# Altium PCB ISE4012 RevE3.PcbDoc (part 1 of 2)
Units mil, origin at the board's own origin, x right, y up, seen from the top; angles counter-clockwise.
Board outline 4950 x 3450 mil, 4 copper layers (Top Layer, InternalPlane1, MidLayer1, Bottom Layer), stack 59 mil thick; 143 components, 94 nets, 413 pads, 604 vias.
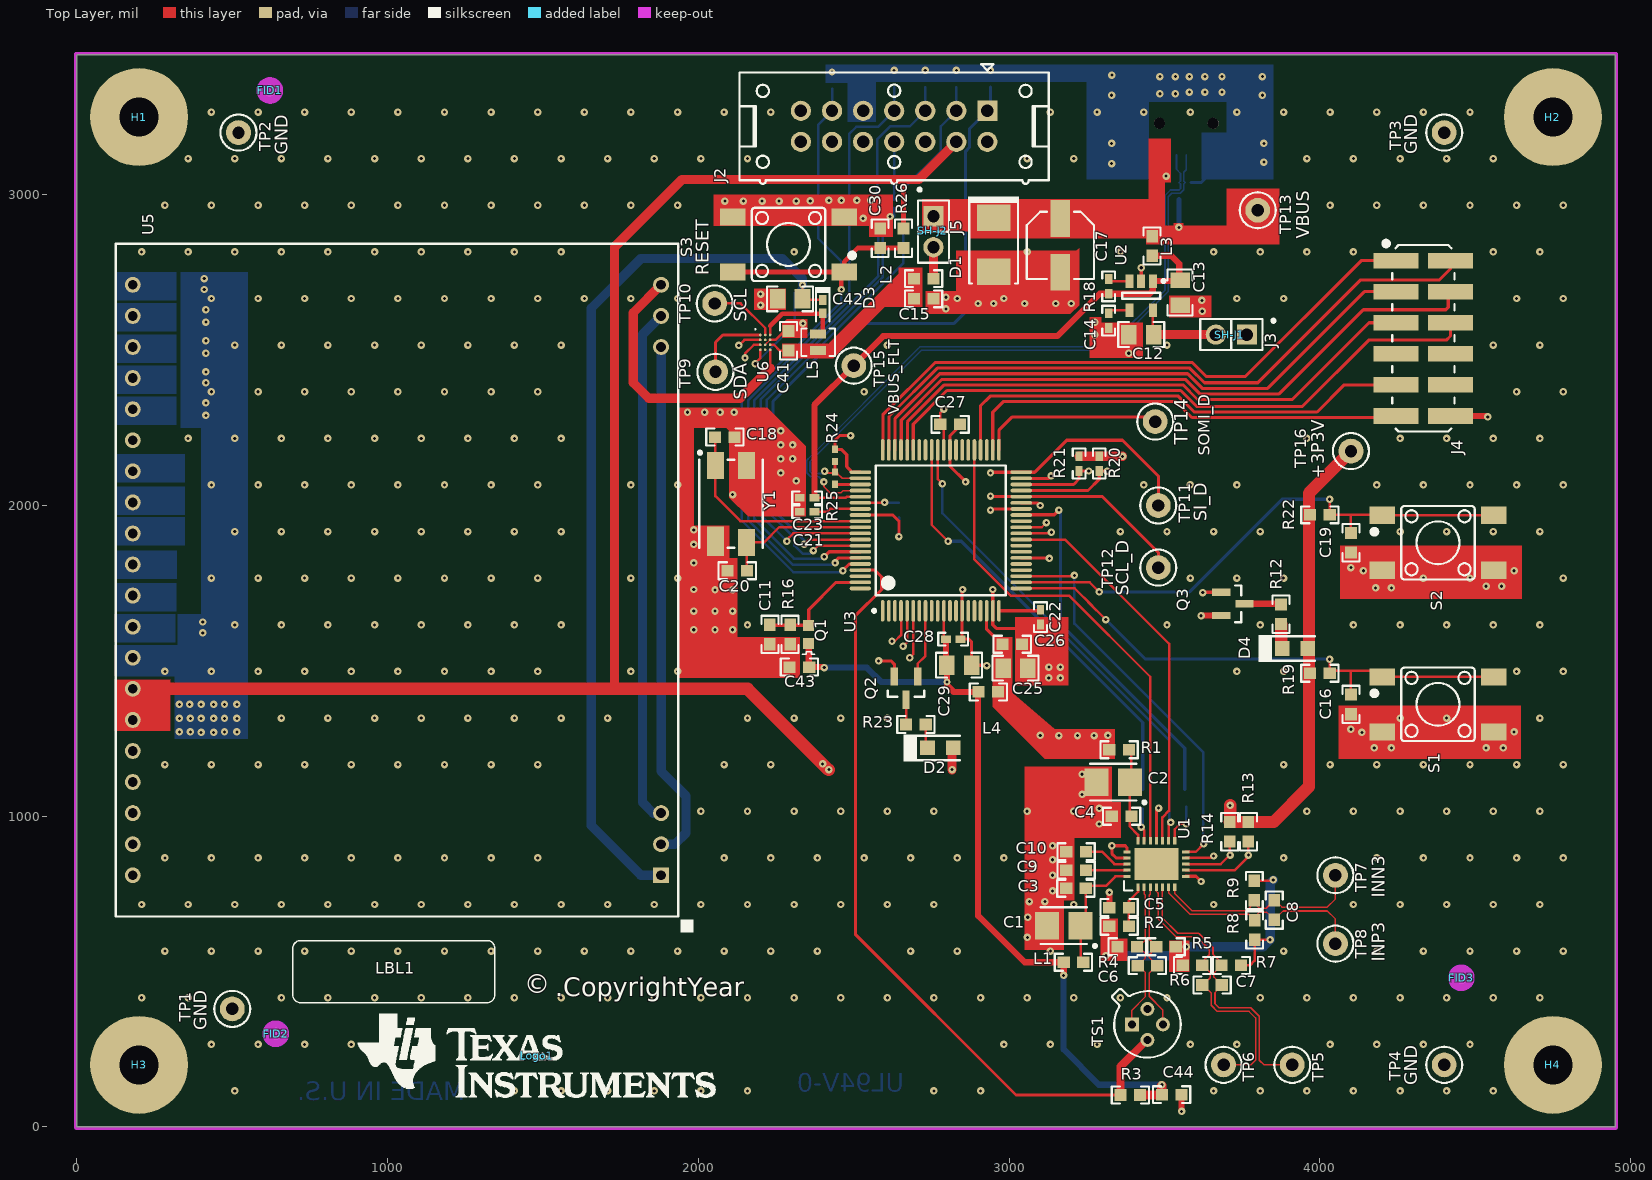
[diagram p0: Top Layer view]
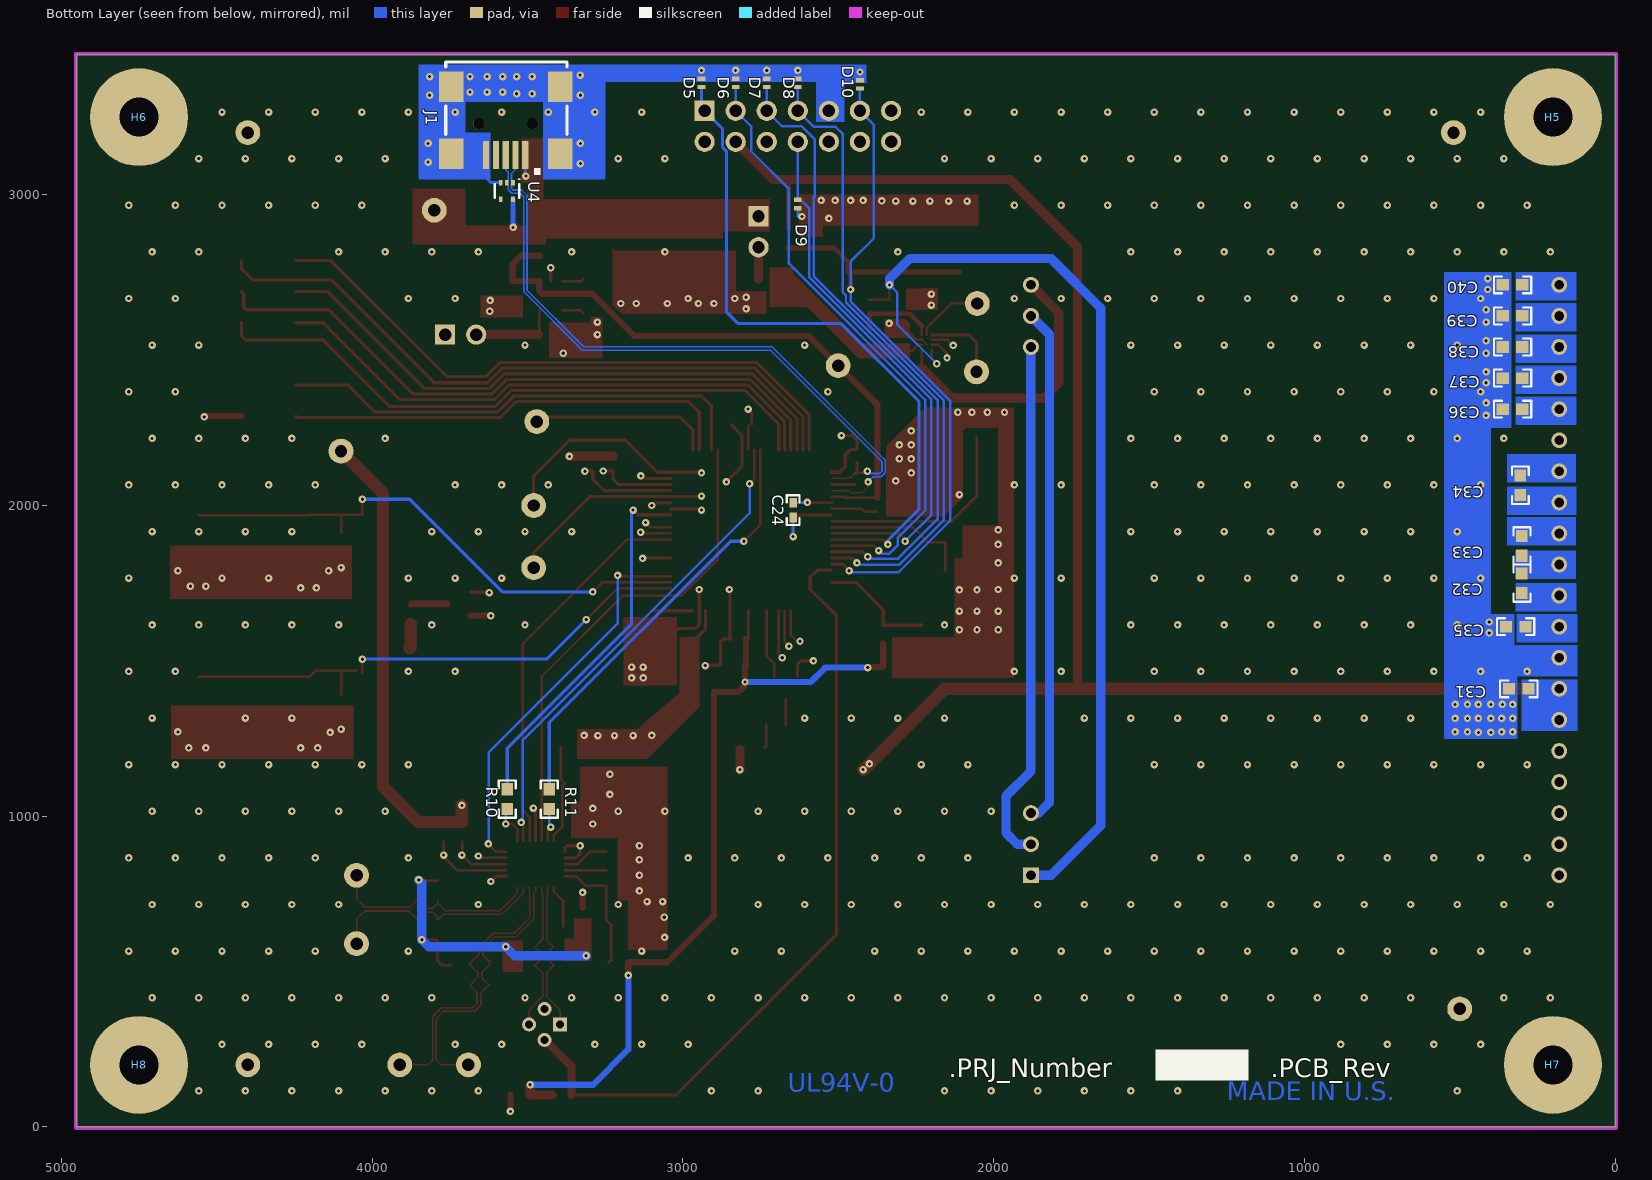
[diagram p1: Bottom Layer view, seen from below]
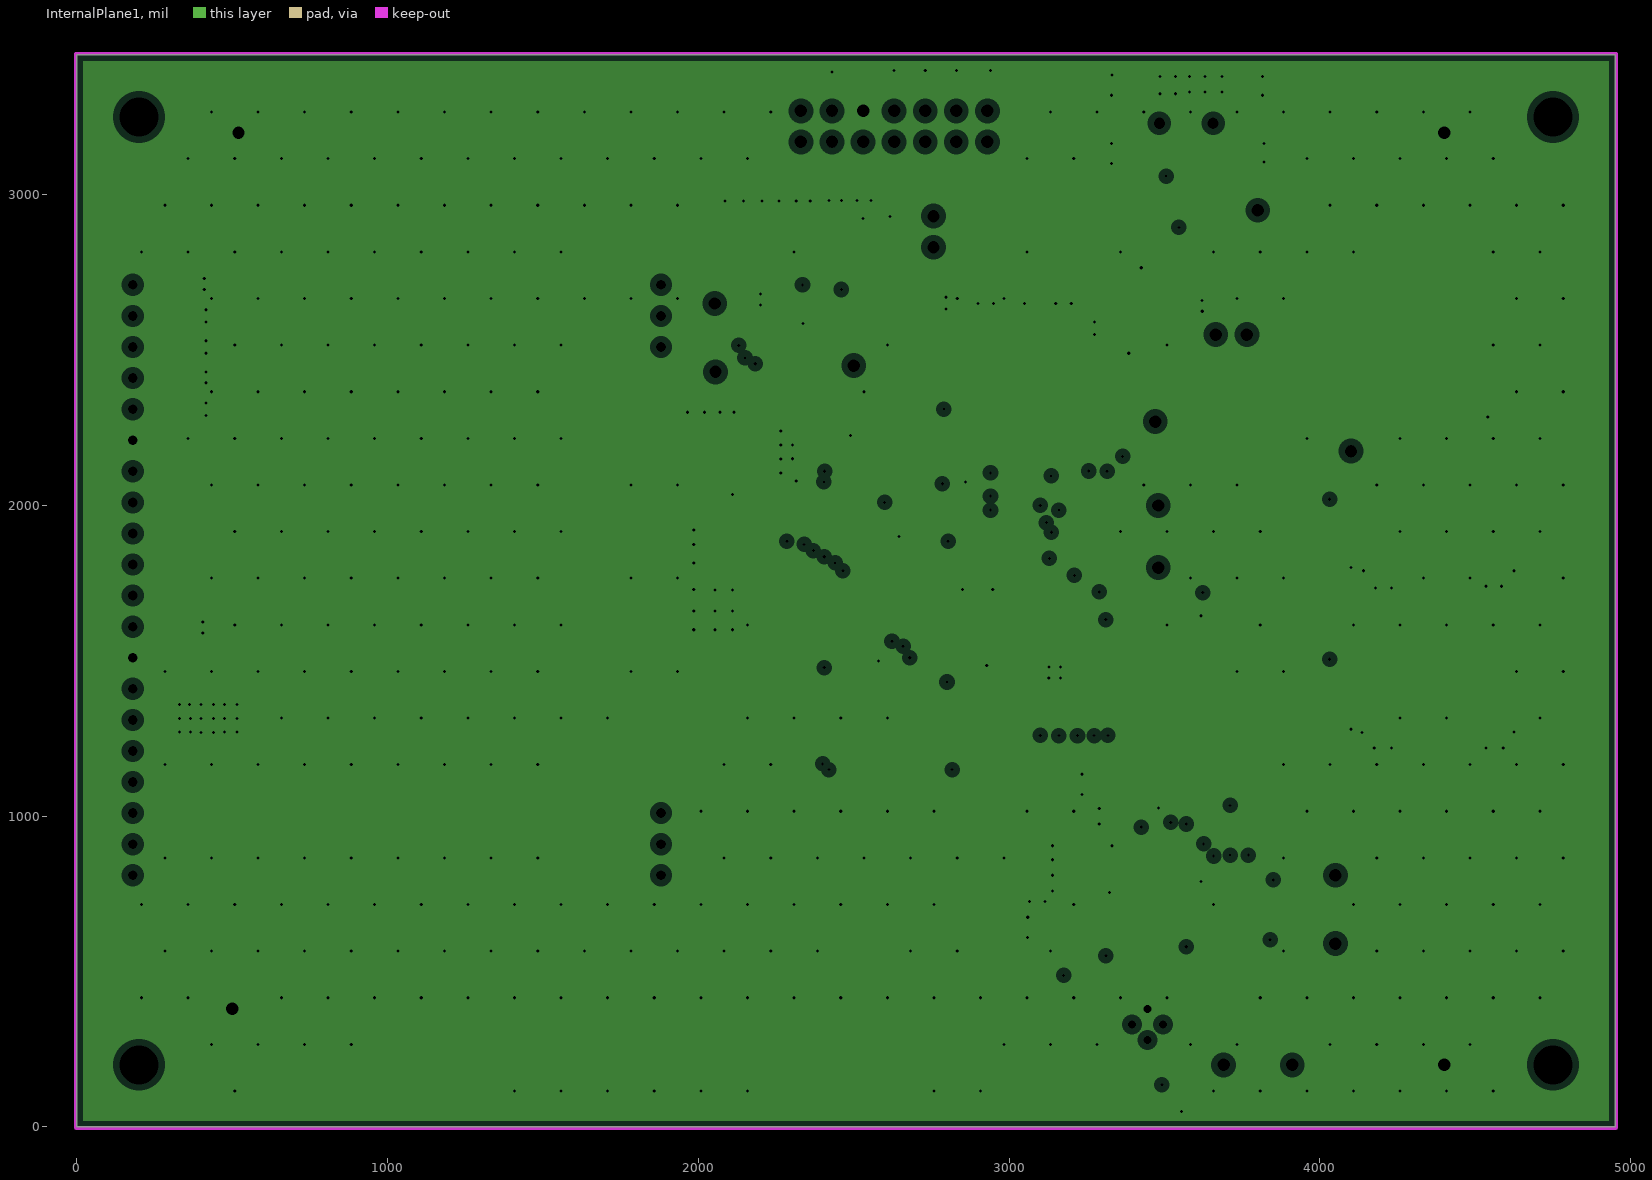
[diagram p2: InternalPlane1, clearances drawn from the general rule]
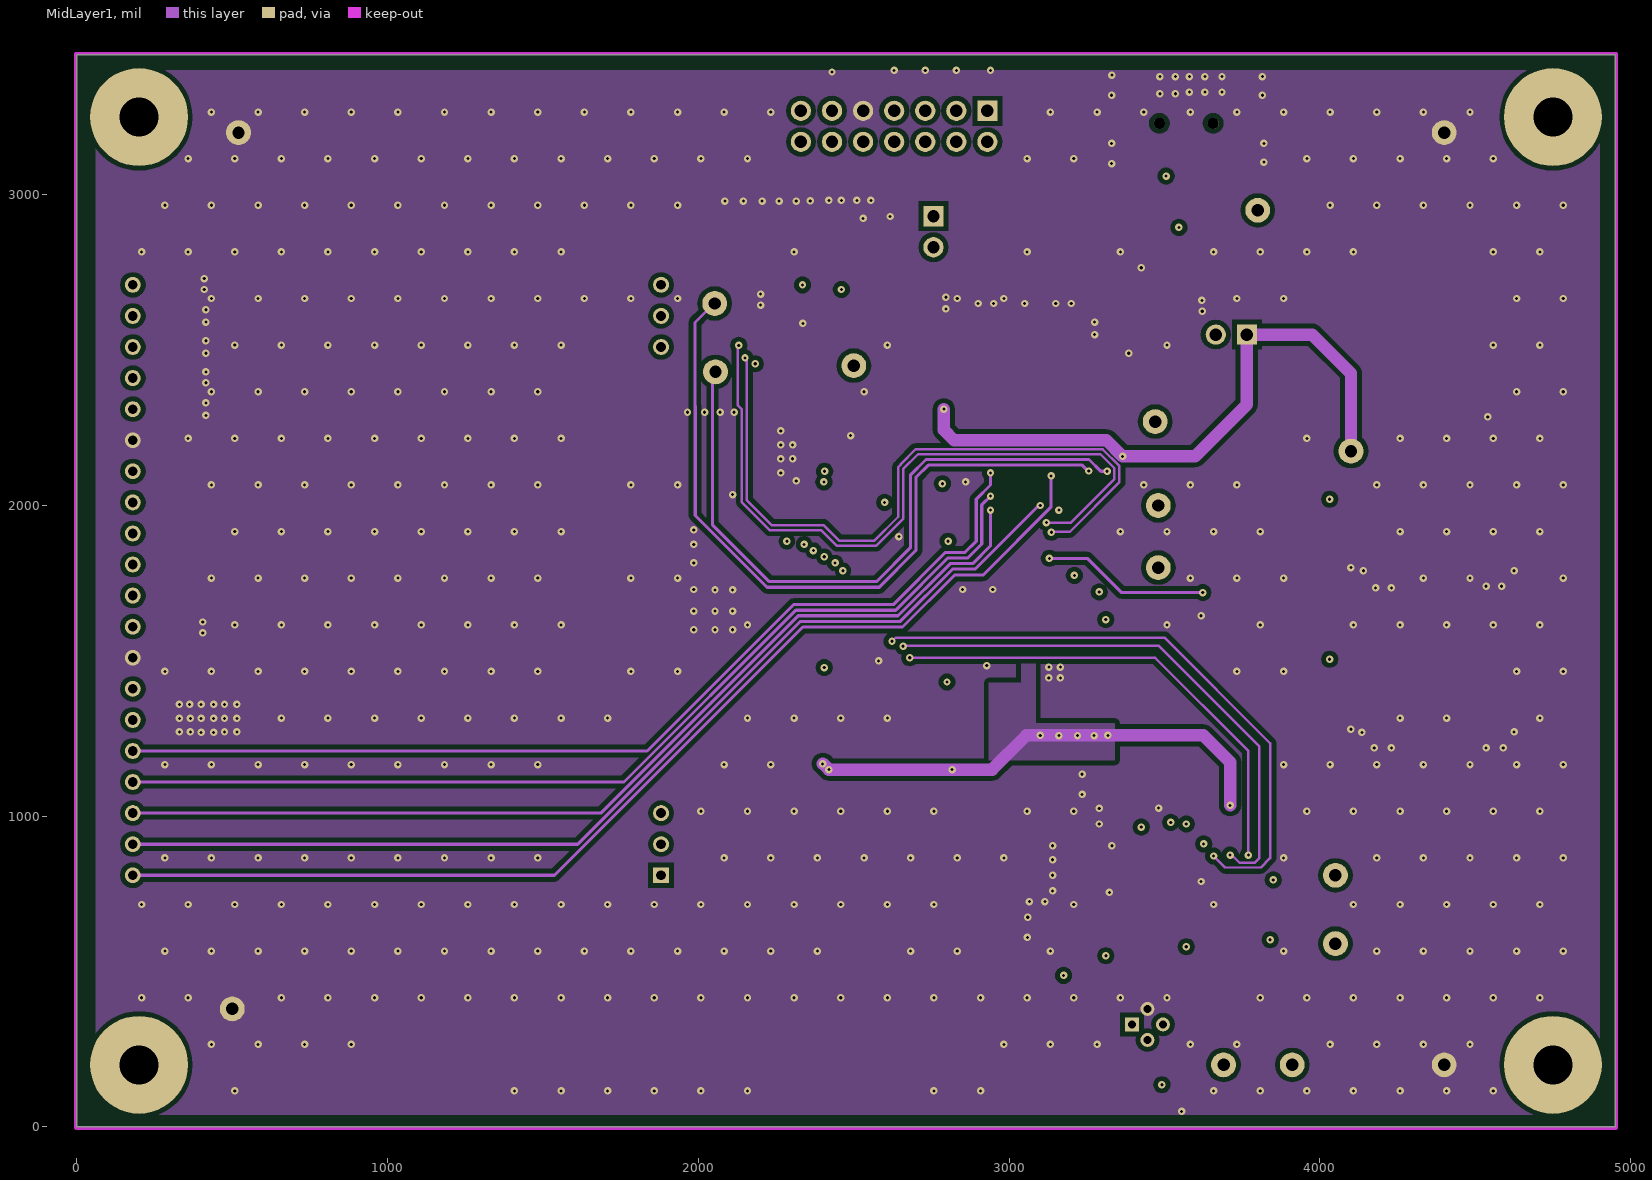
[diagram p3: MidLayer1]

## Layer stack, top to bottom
Top Layer: signal copper 1.4
Dielectric: prepreg 5.2, 370HR, Dk 4.8
InternalPlane1: plane copper 1.4, net GND
Dielectric: core 43, 370HR, Dk 4.8
MidLayer1: signal copper 1.4
Dielectric: prepreg 5.2, 370HR, Dk 4.8
Bottom Layer: signal copper 1.4

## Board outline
0,0 4950,0 4950,3450 0,3450

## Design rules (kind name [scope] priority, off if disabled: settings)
AcuteAngle [All] p1: minimum=4.50000000000000E+0001 checktracksonly=FALSE
AssemblyTestPointUsage [All] p1: valid=2
Clearance Clearance_1 [All vs InComponent('U6')] p1: gap=4
Clearance Clearance_BoardEdge_MountingHoles [OnCopper and InComponentClass('Mounting Holes') vs IsKeepOut] p2: gap=40
Clearance Clearance_BoardEdge_Poly [OnCopper and InPoly vs IsKeepOut] p3: gap=10
Clearance Clearance_BoardEdge [OnCopper and Not InComponentClass('Logo') and not InComponentClass('FiducialMark') and not InRegion(1000,500,4000,800) and Not IsKeepout vs IsKeepOut] p4: gap=10
Clearance Clearance_Poly [InPolygon] p5: gap=15
Clearance [All] p6: gap=5
ComponentClearance ComponentClearance_Shunt [InComponentClass('Header') vs InComponentClass('Shunt')] p1: gap=0 collisioncheckmode=3 verticalgap=0 showdistances=FALSE
ComponentClearance ComponentClearance_Logo [InComponentClass('Logo')] p2 off: gap=50 collisioncheckmode=3 verticalgap=10 showdistances=FALSE
ComponentClearance ComponentClearance_ScrewToNut [(HasFootprint('NY PMS 440 0025 PH')) vs (HasFootprint('Keystone_1902C'))] p3 off: gap=5 collisioncheckmode=3 verticalgap=10 showdistances=FALSE
ComponentClearance ComponentClearance_MountingHoles [InComponentClass('Mounting Holes')] p4 off: gap=20 collisioncheckmode=3 verticalgap=100000 showdistances=FALSE
ComponentClearance ComponentClearance_SmallPassives [HasFootprint('0201*') or HasFootprint('0402*') or HasFootprint('0508') or HasFootprint('0603*') or HasFootprint('0612') or HasFootprint('0805*') or HasFootprint('0815*') or HasFootprint('0830*') or HasFootprint('1206*') or HasFootprint('1210*') or HasFootprint('1808*') or HasFootprint('1812*') or HasFootprint('1825*') or HasFootprint('2010*') or HasFootprint('2220*') or HasFootprint('2225*') or HasFootprint('2512*') or HasFootprint('2728*') or HasFootprint('3518*') vs HasFootprint('0201*') or HasFootprint('0402*') or HasFootprint('0508') or HasFootprint('0603*') or HasFootprint('0612') or HasFootprint('0805*') or HasFootprint('0815*') or HasFootprint('0830*') or HasFootprint('1206*') or HasFootprint('1210*') or HasFootprint('1808*') or HasFootprint('1812*') or HasFootprint('1825*') or HasFootprint('2010*') or HasFootprint('2220*') or HasFootprint('2225*') or HasFootprint('2512*') or HasFootprint('2728*') or HasFootprint('3518*')] p5 off: gap=20 collisioncheckmode=3 verticalgap=10 showdistances=FALSE
ComponentClearance ComponentClearance_THtoSMT [IsThruComponent vs IsSMTComponent] p6 off: gap=100 collisioncheckmode=3 verticalgap=30 showdistances=FALSE
ComponentClearance ComponentClearance_THtoTH [IsThruComponent vs IsThruComponent] p7 off: gap=118.11 collisioncheckmode=3 verticalgap=30 showdistances=FALSE
ComponentClearance [All] p8 off: gap=10 collisioncheckmode=3 verticalgap=10 showdistances=FALSE
DiffPairsRouting [All] p1: maxlimit=100 minlimit=4 mostfreqgap=5 maxuncoupledlength=1900
FabricationTestPointUsage TestPointUsage [All] p1: valid=2 allowmultiple=FALSE
FabricationTestpoint Testpoint [All] p1: side=3 testpointundercomponent=TRUE minsize=40 maxsize=100 preferedsize=60 minholesize=0 maxholesize=40 preferedholesize=32 testpointgrid=1 allowsidetop=TRUE allowsidebottom=TRUE usegrid=TRUE gridtolerance=0.01
FanoutControl Fanout_LCC [IsLCC] p1: bgadir=Out bgaviamode=Centered fanoutstyle=Auto fanoutdirection=Alternating viagrid=1 // Fanout_LCC (Default Rule)
FanoutControl Fanout_BGA [IsBGA] p2: bgadir=Out bgaviamode=Centered fanoutstyle=Auto fanoutdirection=Alternating viagrid=1 // Fanout_BGA (Default Rule)
FanoutControl Fanout_Default [All] p4: bgadir=Out bgaviamode=Centered fanoutstyle=Auto fanoutdirection=Alternating viagrid=1 // Fanout_Default (Default Rule)
FanoutControl Fanout_Small [(CompPinCount < 5)] p5: bgadir=Out bgaviamode=Centered fanoutstyle=Auto fanoutdirection=OutThenIn viagrid=1 // Fanout_Small (Default Rule)
HoleSize [All] p1: absolutevalues=TRUE maxlimit=251 minlimit=6 maxpercent=80.000 minpercent=20.000
MinimumAnnularRing MinimumAnnularRing_ThermalPadVias [IsVia and InAnyComponent] p1: minimumring=3
MinimumAnnularRing [All] p2: minimumring=2
MinimumSolderMaskSliver MinimumSolderMaskSliver_Logo [InComponentClass('Logo') vs InComponentClass('Logo')] p1: minsoldermaskwidth=0.7
MinimumSolderMaskSliver [All] p2: minsoldermaskwidth=3
PlaneClearance [All] p1: clearance=20
PlaneConnect [All] p1: planeconnectstyle=Relief reliefexpansion=10 reliefentries=4 reliefconductorwidth=10 reliefairgap=10
PolygonConnect [All] p1: connectstyle=Direct reliefconductorwidth=10 reliefentries=4 polygonreliefangle="90 Angle" airgapwidth=10
RoomDefinition "ISE4012 sheet5" [InComponentClass('ISE4012 sheet5')] p1: confinementstyle=ConfineIn formatcopy=TRUE lockcomponents=FALSE outline -692,-1534 1308,-1534 1308,-534 -692,-534
RoomDefinition "ISE4012 sheet4" [InComponentClass('ISE4012 sheet4')] p2: confinementstyle=ConfineIn formatcopy=TRUE lockcomponents=FALSE outline -692,-1534 1308,-1534 1308,-534 -692,-534
RoutingVias ThermalPadVias [IsVia and InAnyComponent] p1: holewidth=7.87 width=19.68 viastyle="Through Hole" minholewidth=6 minwidth=10 maxholewidth=25 maxwidth=50
RoutingVias [All] p2: holewidth=16 width=34 viastyle="Through Hole" minholewidth=5 minwidth=10 maxholewidth=40 maxwidth=65
SMDToCorner [All] p1: distance=30000
SilkToSilkClearance [All] p1: silktosilkclearance=5
SilkscreenOverComponentPads [All] p1: minsilkscreentomaskgap=5
SolderMaskExpansion [All] p1: expansion=1.97
Width "Schematic Width Constraint_4" [InNet('VBUS_FLT')] p1: maxlimit=100 minlimit=5 preferedwidth=25
Width "Schematic Width Constraint_3" [InNet('+3P3V')] p2: maxlimit=100 minlimit=5 preferedwidth=25
Width "Schematic Width Constraint_2" [InNet('+3P3V_OUT')] p3: maxlimit=100 minlimit=5 preferedwidth=25
Width "Schematic Width Constraint_1" [InNet('+5V')] p4: maxlimit=100 minlimit=5 preferedwidth=25
Width "Schematic Width Constraint" [InNet('VBUS')] p5: maxlimit=100 minlimit=5 preferedwidth=25
Width [All] p6: maxlimit=100 minlimit=4 preferedwidth=10 minimp=50.000000 maximp=50.000000 favimp=50.000000 checkconnectedcopper=TRUE
13 further rules are at their usual default settings.

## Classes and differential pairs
component class "Mounting Holes": H1 H2 H3 H4
component class Logo: Logo1
component class "ISE4012 sheet2": FID1 FID2 FID3 H1 H2 H3 H4 H5 H6 H7 H8 LBL1 Logo1 ZZ1 ZZ2 ZZ3 ZZ4 ZZ5 ZZ6 ZZ6.A ZZ6.B ZZ6.C ZZ6.D
component class FiducialMark: FID1 FID2 FID3
component class AssemblyNote: ZZ1 ZZ2 ZZ3 ZZ4 ZZ5 ZZ6 ZZ6.A ZZ6.B ZZ6.C ZZ6.D
component class Label: LBL1
component class "ISE4012 sheet3": C1 C2 C3 C4 C5 C6 C7 C8 C9 C10 C11 C43 C44 L1 Q1 R1 R2 R3 R4 R5 R6 R7 R8 R9 R10 R11 R13 R14 R16 TP1 TP2 TP3 TP4 TP5 TP6 TP7 TP8 TS1 U1
component class "ISE4012 sheet4": C12 C13 C14 C15 C16 C17 C18 C19 C20 C21 C22 C23 C24 C25 C26 C27 C28 C29 C30 D1 D2 D4 D5 D6 D7 D8 D9 D10 J1 J2 J3 J4 J5 L2 L3 L4 Q2 Q3 R12 R18 R19 R20 R21 R22 R23 R24 R25 R26 S1 S2 S3 SH-J1 SH-J2 TP9 TP10 TP12 TP13 TP14 TP16 U2 U4 Y1
component class "ISE4012 sheet5": C31 C32 C33 C34 C35 C36 C37 C38 C39 C40 C41 C42 D3 L5 TP11 TP12 U5 U6
component class Shunt: SH-J1 SH-J2
differential pair USB_D: +USB_D_P -USB_D_N

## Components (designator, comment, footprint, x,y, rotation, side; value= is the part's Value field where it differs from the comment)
C1 "TPSB106K016R0800" 3528-21 3176,648 r180 top
C2 "TPSB106K016R0800" 3528-21 3335,1110 r180 top
C3 "06033C104JAT2A" 0603 3215,768 r180 top
C4 "06033C104JAT2A" 0603 3362,1000 r0 top
C5 "06033C104JAT2A" 0603 3353.94,706.06 r180 top
C6 "06033C104JAT2A" 0603 3445,519 r0 top
C7 "06033C104JAT2A" 0603 3653,457 r0 top
C8 "06033C104JAT2A" 0603 3853,698 r90 top
C9 "C1608X7R1C105K" 0603 3215.43,826.06 r180 top
C10 "06033C104JAT2A" 0603 3215.43,886.06 r180 top
C11 "06033C104JAT2A" 0603 2230,1585 r270 top
C12 "0805ZD475KAT2A" 0805_HV 3425,2550 r180 top
C13 "C0805C225K8PACTU" 0805_HV 3550,2685 r270 top
C14 "GRM155R71C103KA01D" 0402 3320,2595 r270 top
C15 "C1608X7R1C105K" 0603 2725,2665 r0 top
C16 "06031C222JAT2A" 0603 4100,1360 r270 top
C17 "EEE-1AA220WR" CAPSMT_62_E55 3165,2837 r270 top
C18 "06035A180JAT2A" 0603 2085,2220 r0 top
C19 "06031C222JAT2A" 0603 4100,1880 r270 top
C20 "06035A180JAT2A" 0603 2125,1790 r180 top
C21 "GRM155R61A224KE19D" 0402 2350,1980 r180 top
C22 "GRM155R61A474KE15D" 0402 3101,1640.62 r270 top
C23 "GRM155R61A224KE19D" 0402 2350,2025 r180 top
C24 "GRM155R61A224KE19D" 0402 2645,1985 r270 bottom
C25 "C0805C106K8PACTU" 0805_HV 3020.5,1476.5 r0 top
C26 "06033C104JAT2A" 0603 3010,1553.5 r0 top
C27 "06033C104JAT2A" 0603 2810,2261 r0 top
C28 "GRM155R61C104KA88D" 0402 2820,1570 r0 top
C29 "C0805C106K8PACTU" 0805_HV 2839,1486 r0 top
C30 "06031C222JAT2A" 0603 2585,2860 r90 top
C31 "C1608X7R1C105K" 0603 310,1410 r0 bottom
C32 "C1608X7R1C105K" 0603 300,1750 r90 bottom
C33 "C1608X7R1C105K" 0603 300,1870 r90 bottom
C34 "C1608X7R1C105K" 0603 305,2065 r90 bottom
C35 "C1608X7R1C105K" 0603 320,1610 r0 bottom
C36 "C1608X7R1C105K" 0603 330,2310 r0 bottom
C37 "C1608X7R1C105K" 0603 330,2410 r0 bottom
C38 "C1608X7R1C105K" 0603 330,2510 r0 bottom
C39 "C1608X7R1C105K" 0603 330,2610 r0 bottom
C40 "C1608X7R1C105K" 0603 330,2710 r0 bottom
C41 "C0603C225K8PACTU" 0603 2290,2530 r90 top
C42 "GRM21BR71H105KA12L" 0805_HV 2295,2665 r180 top
C43 "06033C104JAT2A" 0603 2325,1480 r180 top
C44 "06033C104JAT2A" 0603 3523,104 r0 top
D1 "1SMB5922BT3G" SMB 2950,2839 r270 top
D2 "LTST-C190GKT" LED_LTST-C171 2778.5,1220 r180 top
D3 "NSR0240V2T1G" SOD-523 2400,2640 r270 top
D4 "LTST-C190GKT" LED_LTST-C171 3920,1540 r180 top
D5 "TPD1E10B06DPYR" DPY0002A_N 2940,3360 r90 bottom
D6 "TPD1E10B06DPYR" DPY0002A_N 2830,3360 r90 bottom
D7 "TPD1E10B06DPYR" DPY0002A_N 2730,3360 r90 bottom
D8 "TPD1E10B06DPYR" DPY0002A_N 2630,3360 r90 bottom
D9 "TPD1E10B06DPYR" DPY0002A_N 2630,2970 r270 bottom
D10 "TPD1E10B06DPYR" DPY0002A_N 2430,3355 r90 bottom
FID1 "Fiducial" Fiducial10-20 621,3335.5 r0 top
FID2 "Fiducial" Fiducial10-20 640,300 r0 top
FID3 "Fiducial" Fiducial10-20 4455,480 r0 top
H1 "NY PMS 440 0025 PH" "NY PMS 440 0025 PH" 200,3250 r0 top locked
H2 "NY PMS 440 0025 PH" "NY PMS 440 0025 PH" 4750,3250 r0 top locked
H3 "NY PMS 440 0025 PH" "NY PMS 440 0025 PH" 200,200 r0 top locked
H4 "NY PMS 440 0025 PH" "NY PMS 440 0025 PH" 4750,200 r0 top locked
H5 "1902C" Keystone_1902C 200,3250 r180 bottom locked
H6 "1902C" Keystone_1902C 4750,3250 r180 bottom locked
H7 "1902C" Keystone_1902C 200,200 r180 bottom locked
H8 "1902C" Keystone_1902C 4750,200 r180 bottom locked
J1 "1734035-2" CONN_USB-Mini-B-1734035-2 3570,3230 r0 bottom
J2 "SBH11-PBPC-D07-ST-BK" CONN_SBH11-PBPC-D07-ST-BK 2630,3220 r180 top
J3 "90120-0122" CONN_90120-0122 3715,2550 r180 top
J4 "0015912120" MOLEX_0015912120 4333,2538 r270 top
J5 "90120-0122" CONN_90120-0122 2756.5,2881 r270 top
L1 "BLM18SG260TN1D" 0603 3207,530 r180 top
L2 "BLM18SG331TN1D" 0603 2725,2730 r180 top
L3 "BLM18SG331TN1D" 0603 3460,2835 r270 top
L4 "BLM18SG331TN1D" 0603 2933,1400 r180 top
L5 "VLF252015MT-100M" IND_VLF252015 2385,2525 r90 top
LBL1 "Size: 0.65\" x 0.20 \"" Label_650x200 1020,500 r0 top
Logo1 "Texas Instruments" TI_Stacked_Overlay_Medium 1480,230 r0 top
Q1 "ALS-PT19-315C/L177/TR8" ALS-PT19-315C-L177-TR8 2355,1585 r90 top
Q2 "BSS138" SOT-23 2668.19,1412.08 r270 top
Q3 "BSS138" SOT-23 3720,1683.5 r0 top
R1 "CRCW06030000Z0EA" 0603 3354,1214 r180 top
R2 "CRCW06030000Z0EA" 0603 3353.94,646.06 r0 top
R3 "CRCW0603649KFKEA" 0603 3390,103 r0 top
R4 "RC0603FR-072M21L" 0603 3380,580 r180 top
R5 "RC0603FR-072M21L" 0603 3505,580 r0 top
R6 "RC0603FR-072M21L" 0603 3590,520 r180 top
R7 "RC0603FR-072M21L" 0603 3715,520 r0 top
R8 "RC0603FR-072M21L" 0603 3790,634 r270 top
R9 "RC0603FR-072M21L" 0603 3789,761 r90 top
R10 "CRCW060349R9FKEA" 0603 3565,1055 r90 bottom
R11 "CRCW060349R9FKEA" 0603 3430,1055 r90 bottom
R12 "CRCW0603200RJNEA" 0603 3875,1650 r270 top
R13 "CRCW06031M00JNEA" 0603 3770,950 r90 top
R14 "CRCW06031M00JNEA" 0603 3710,950 r90 top
R16 "CRCW06031K00FKEA" 0603 2295,1585 r90 top
R18 "CRCW04020000Z0ED" 0402 3320,2705 r270 top
R19 "CRCW060347K5FKEA" 0603 4000,1460 r180 top
R20 "CRCW04024K99FKED" 0402 3290,2135 r90 top
R21 "CRCW04024K99FKED" 0402 3225,2135 r90 top
R22 "CRCW060347K5FKEA" 0603 4000,1970 r180 top
R23 "CRCW0603200RJNEA" 0603 2700,1295 r0 top
R24 "CRCW04021M00FKED" 0402L 2440,2161 r90 top
R25 "CRCW04021K50FKED" 0402L 2440,2088 r90 top
R26 "CRCW060347K5FKEA" 0603 2660,2860 r90 top
S1 "4-1437565-1" SW_FSM4JSMA 4380,1360 r90 top
S2 "4-1437565-1" SW_FSM4JSMA 4380,1880 r90 top
S3 "4-1437565-1" SW_FSM4JSMA 2290,2840 r270 top
SH-J1 "2SN-BK-G" 2SN-BK-G 3710,2550 r180 top
SH-J2 "2SN-BK-G" 2SN-BK-G 2753.5,2884.5 r90 top
TP1 "5000" Keystone5000 500,380 r90 top
TP2 "5000" Keystone5000 520,3200 r90 top
TP3 "5000" Keystone5000 4400,3200 r90 top
TP4 "5000" Keystone5000 4400,200 r90 top
TP5 "5001" Keystone5001 3911,200 r90 top
TP6 "5001" Keystone5001 3690,200 r90 top
TP7 "5001" Keystone5001 4050,810 r90 top
TP8 "5001" Keystone5001 4050,590 r90 top
TP9 "5003" Keystone5003 2055,2430 r0 top
TP10 "5004" Keystone5004 2052.5,2650 r0 top
TP11 "5003" Keystone5003 3480,2000 r90 top
TP12 "5004" Keystone5004 3480,1800 r90 top
TP13 "5000" Keystone5000 3800,2950 r90 top
TP14 "5000" Keystone5000 3470,2270 r180 top
TP15 "5000" Keystone5000 2500,2450 r90 top
TP16 "5000" Keystone5000 4100,2175 r90 top
TS1 "ZTP-135SR" TO-46 3445,330 r0 top
U1 "LMP93601NHZ" NHZ0024B 3473.94,846.06 r90 top
U2 "LP2985AIM5-3.3/NOPB" MF05A_N 3425,2675 r270 top
U3 "MSP430F5529IPN" PN0080A_N 2780,1920 r90 top
U4 "TPD3E001DRLR" DRL0005A 3566.5,3012.5 r270 bottom
U5 "EA DOGM128W-6" "LCD-MODULE_EA DOGM128W-6" 1030,1760 r90 top
U6 "LM3630ATME" YFQ0012AKAR 2215,2525 r0 top
Y1 "ABMM-24.000MHZ-B2-T" Abracon_ABMM 2105,2005 r0 top
ZZ1 "This Assembly Note is for PCB labels only" AssemblyNoteLabel 190,4490 r0 top
ZZ2 "These assemblies are ESD sensitive, ESD precautions shall be observed." AssemblyNote 190,4430 r0 top
ZZ3 "These assemblies must be clean and free from flux and all contaminants. Use of no clean flux is not acceptable." AssemblyNote 190,4370 r0 top
ZZ4 "These assemblies must comply with workmanship standards IPC-A-610 Class 2, unless otherwise specified." AssemblyNote 190,4310 r0 top
ZZ5 "Place SH-J1 on J3 and SH-J2 on J5 (pins 1-2)" AssemblyNote 190,4250 r90 top
ZZ6 "Component BL1 must be assembled to U5 Before U5 is attached to the board." AssemblyNote 190,4190 r0 top
ZZ6.A "Remove protective coverings from BL1 and U5" AssemblyNote 300,4120 r0 top
ZZ6.B "Slide pins of U5 into holes of BL1. BL1 must lie flat on the back of U5." AssemblyNote 300,4050 r0 top
ZZ6.C "Solder U5 - BL1 assembly to the board." AssemblyNote 300,3990 r0 top
ZZ6.D "Solder Pins 1, 2, 3, 18, 19, and 20 of U5 to BL1 from the top to insure electrical continuity." AssemblyNote 300,3920 r0 top

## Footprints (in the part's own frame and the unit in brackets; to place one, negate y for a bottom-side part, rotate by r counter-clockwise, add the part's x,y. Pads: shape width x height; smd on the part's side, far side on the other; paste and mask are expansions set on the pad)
2SN-BK-G [mil] "Samtec STEP model"
  round 1 on Mech3: 0(0,0)
  body extent -78,-39 79,39, height 188
0402 [mm] "0402 from SM-752 data"
  rect 0.8x0.6 smd: 1(-0.6,0) 2(0.6,0)
  silkscreen extent -1.22,-0.52 1.22,0.52, body extent -0.55,-0.3 0.55,0.3, height 0.6
0402L [mm] "0402 from SM-752 data"
  rect 0.6x0.5 smd: 1(-0.5,0) 2(0.5,0)
  body extent -0.55,-0.3 0.55,0.3, height 0.6
0603 [mm] "0603 from SM-752 data"
  rect 1x0.95 smd: 1(-0.8,0) 2(0.8,0)
  silkscreen extent -1.52,-0.69 1.52,0.69, body extent -0.87,-0.47 0.87,0.47, height 0.85
0805_HV [mil] "0805 with 30mil clearance between pads"
  rect 50x63 smd: 1(-40,0) 2(40,0)
  silkscreen extent -74,-40 74,40, body extent -43,-29 43,29, height 43
3528-21 [mm] "Medium Density IPC, based on SM-782 section 8.4"
  rect 1.95x2.25 smd: 1(-1.375,0) 2(1.375,0)
  silkscreen extent -2.66,-1.5 1.9,1.79, body extent -1.85,-1.5 1.85,1.5, height 2.1
Abracon_ABMM [mm] "Abracon"
  rect 1.4x2.2 smd: 1(-1.27,3.15) 2(1.27,3.15) 3(1.27,-3.15)
  rect 1.4x2.4 smd: 4(-1.27,-3.05)
  silkscreen extent -2.67,-3.6 2.6,4.32, body extent -2.6,-3.6 2.6,3.6, height 1.3
ALS-PT19-315C-L177-TR8 [mm] "EVERLIGHT"
  rect 0.9x0.9 smd: 1(-0.75,0) 2(0.75,0)
  silkscreen extent -1.63,-0.5 -1.43,0.5, body extent -0.95,-0.5 0.95,0.5, height 0.7
AssemblyNote [mil] "Assembly Note"
AssemblyNoteLabel [mil] "Assembly Note for PCB Labels"
CAPSMT_62_E55 [mm] "5 x 5.2mm:  Chemi-Con E55"
  rect 3x1.6 smd: 1(-2.2,0) 2(2.2,0)
  silkscreen extent -2.75,-2.75 2.75,2.75, body extent -2.76,-2.76 2.76,2.76, height 5.5
CONN_90120-0122 [mm] "Molex"
  rect 1.65x1.65 hole 1.016 mask+0: 1(-1.27,0)
  round 1.65 hole 1.016 mask+0: 2(1.27,0)
  silkscreen extent -3.57,-1.27 2.54,1.27, body extent -2.54,-1.27 2.54,1.27, height 9.29
CONN_SBH11-PBPC-D07-ST-BK [mm] "Sullins recommended land pattern"
  rect 1.65x1.65 hole 1.016 mask+0: 1(-7.62,-1.27)
  round 1.65 hole 1.016 mask+0: 2(-7.62,1.27) 3(-5.08,-1.27) 4(-5.08,1.27) 5(-2.54,-1.27) 6(-2.54,1.27) 7(0,-1.27) 8(0,1.27) 9(2.54,-1.27) 10(2.54,1.27) 11(5.08,-1.27) 12(5.08,1.27) 13(7.62,-1.27) 14(7.62,1.27)
  silkscreen extent -12.64,-5.08 12.64,4.7, body extent -12.64,-4.4 12.64,4.7, height 9.12
CONN_USB-Mini-B-1734035-2 [mm] "Tyco Connectivity recommended land pattern"
  rect 0.5x2.3 smd: 1(-1.6,2.6) 2(-0.8,2.6) 3(0,2.6) 4(0.8,2.6) 5(1.6,2.6)
  rect 2x2.5 smd: 6(4.45,2.5) 7(4.45,-3) 8(-4.45,-3) 9(-4.45,2.5)
  round 0.9 hole 0.9 unplated: 10(2.2,0) 11(-2.2,0)
  silkscreen extent -5,-5 4.9,4.19, body extent -4.95,-5.9 4.95,3.3, height 4.1
DPY0002A_N [mm] "DFN, 2-Leads, Body 1.0x0.6x0.4mm, IPC Medium Density"
  rect 0.35x0.62 smd: 1(-0.34,0) 2(0.34,0)
  body extent -0.5,-0.3 0.5,0.3, height 0.4
DRL0005A [mm] "SOTFL, 5-Flat Leads, Body 1.2x1.6x0.6mm, Pitch 0.5mm, TI Recommended"
  rect 0.45x0.3 smd: 1(-0.675,0.5) 2(-0.675,0) 3(-0.675,-0.5) 4(0.675,-0.5) 5(0.675,0.5)
  silkscreen extent -1,-1 0.55,1.05, body extent -0.65,-0.85 0.65,0.85, height 0.6
Fiducial10-20 [mm]
  round 1 smd paste-0.5 mask+0.5: 1(0,0)
  Top Layer keep-out circle w1.178: c0,0 r0.5
IND_VLF252015 [mm] "TDK"
  rect 0.75x1.3 smd: 1(-0.675,0) 2(0.675,0)
  silkscreen extent -1.12,-1.38 1.12,1.38, body extent -1.1,-1.35 1.1,1.35, height 1.5
Keystone5000 [mil] "For Keystone 500x miniature loop terminals"
  round 80 hole 40: 1(0,0)
  silkscreen extent -58,-58 58,58, body extent -49,-49 49,49, height 182
Keystone5001 [mil] "For Keystone 500x miniature loop terminals"
  round 80 hole 40: 1(0,0)
  silkscreen extent -58,-58 58,58, body extent -49,-49 49,49, height 182
Keystone5003 [mil] "For Keystone 500x miniature loop terminals"
  round 80 hole 40: 1(0,0)
  silkscreen extent -58,-58 58,58, body extent -49,-49 49,49, height 182
Keystone5004 [mil] "For Keystone 500x miniature loop terminals"
  round 80 hole 40: 1(0,0)
  silkscreen extent -58,-58 58,58, body extent -49,-49 49,49, height 182
Keystone_1902C [mil] "Hex Standoff, 4-40 threaded, nylon"
  body extent -145,-126 146,126, height 501
Label_650x200 [mil] "Thermal Transfer Label"
  silkscreen extent -325,-100 325,100, body extent -326,-101 326,101, height 1
"LCD-MODULE_EA DOGM128W-6" [mm] "LCD-MODULE"
  rect 1.3x1.3 hole 0.8: 1(-24.13,-21.59)
  round 1.3 hole 0.8: 2(-21.59,-21.59) 3(-19.05,-21.59) 18(19.05,-21.59) 19(21.59,-21.59) 20(24.13,-21.59) 21(24.13,21.59) 22(21.59,21.59) 23(19.05,21.59) 24(16.51,21.59) 25(13.97,21.59) 26(11.43,21.59) 27(8.89,21.59) 28(6.35,21.59) 29(3.81,21.59) 30(1.27,21.59) 31(-1.27,21.59) 32(-3.81,21.59) 33(-6.35,21.59) 34(-8.89,21.59) 35(-11.43,21.59) 36(-13.97,21.59) 37(-16.51,21.59) 38(-19.05,21.59) 39(-21.59,21.59) 40(-24.13,21.59)
  silkscreen extent -28.8,-24.21 27.5,23, body extent -27.5,-23 27.5,23, height 2.2
LED_LTST-C171 [mm] "LITE-ON"
  rect 1.2x1.2 smd: 1(-1.05,0) 2(1.05,0)
  silkscreen extent -1.6,-1.1 3,1.1, body extent -1.05,-0.67 1.05,0.67, height 0.8
MF05A_N [mm] "SOT23, 5-Leads, Body 2.9x1.6mm, Pitch 0.95mm, Lead Span 2.8mm, IPC Medium Density"
  rect 1.1x0.65 smd: 1(-1.2,0.95) 2(-1.2,0) 3(-1.2,-0.95) 4(1.2,-0.95) 5(1.2,0.95)
  silkscreen extent -1.32,-1.55 0.25,1.95, body extent -0.9,-1.55 0.9,1.55, height 1.19
MOLEX_0015912120 [mil] "MOLEX"
  rect 50x144.88 smd: 1(-250,-87.5) 2(-250,87.5) 3(-150,-87.5) 4(-150,87.5) 5(-50,-87.5) 6(-50,87.5) 7(50,-87.5) 8(50,87.5) 9(150,-87.5) 10(150,87.5) 11(250,-87.5) 12(250,87.5)
  silkscreen extent -313,-128 300,100, body extent -300,-137 300,138, height 380
NHZ0024B [mm]
  rect 0.6x0.25 smd mask+0.07: 1(-1.9,1.5) 2(-1.9,1) 3(-1.9,0.5) 4(-1.9,0) 5(-1.9,-0.5) 6(-1.9,-1) 7(-1.9,-1.5) 13(1.9,-1.5) 14(1.9,-1) 15(1.9,-0.5) 16(1.9,0) 17(1.9,0.5) 18(1.9,1) 19(1.9,1.5)
  rect 0.25x0.6 smd mask+0.07: 8(-1,-2.4) 9(-0.5,-2.4) 10(0,-2.4) 11(0.5,-2.4) 12(1,-2.4) 20(1,2.4) 21(0.5,2.4) 22(0,2.4) 23(-0.5,2.4) 24(-1,2.4)
  rect 2.6x3.6 smd paste-2 mask+0.07: 25(0,0)
  silkscreen extent -2.15,1.95 -1.38,2.65, body extent -2.05,-2.55 2.05,2.55, height 0.8
"NY PMS 440 0025 PH" [mm] "4-40 nylon screw and mounting hole"
  round 8 hole 3.2: 1(0,0)
  body extent -3.3,-3.3 3.3,3.3, height 2.69
PN0080A_N [mm] "QFP, 80-Leads, Body 12x12mm, Pitch 0.5mm, IPC Medium Density"
  oval 1.75x0.3 smd: 1(-6.575,4.75) 2(-6.575,4.25) 3(-6.575,3.75) 4(-6.575,3.25) 5(-6.575,2.75) 6(-6.575,2.25) 7(-6.575,1.75) 8(-6.575,1.25) 9(-6.575,0.75) 10(-6.575,0.25) 11(-6.575,-0.25) 12(-6.575,-0.75) 13(-6.575,-1.25) 14(-6.575,-1.75) 15(-6.575,-2.25) 16(-6.575,-2.75) 17(-6.575,-3.25) 18(-6.575,-3.75) 19(-6.575,-4.25) 20(-6.575,-4.75) 41(6.575,-4.75) 42(6.575,-4.25) 43(6.575,-3.75) 44(6.575,-3.25) 45(6.575,-2.75) 46(6.575,-2.25) 47(6.575,-1.75) 48(6.575,-1.25) 49(6.575,-0.75) 50(6.575,-0.25) 51(6.575,0.25) 52(6.575,0.75) 53(6.575,1.25) 54(6.575,1.75) 55(6.575,2.25) 56(6.575,2.75) 57(6.575,3.25) 58(6.575,3.75) 59(6.575,4.25) 60(6.575,4.75)
  oval 0.3x1.75 smd: 21(-4.75,-6.575) 22(-4.25,-6.575) 23(-3.75,-6.575) 24(-3.25,-6.575) 25(-2.75,-6.575) 26(-2.25,-6.575) 27(-1.75,-6.575) 28(-1.25,-6.575) 29(-0.75,-6.575) 30(-0.25,-6.575) 31(0.25,-6.575) 32(0.75,-6.575) 33(1.25,-6.575) 34(1.75,-6.575) 35(2.25,-6.575) 36(2.75,-6.575) 37(3.25,-6.575) 38(3.75,-6.575) 39(4.25,-6.575) 40(4.75,-6.575) 61(4.75,6.575) 62(4.25,6.575) 63(3.75,6.575) 64(3.25,6.575) 65(2.75,6.575) 66(2.25,6.575) 67(1.75,6.575) 68(1.25,6.575) 69(0.75,6.575) 70(0.25,6.575) 71(-0.25,6.575) 72(-0.75,6.575) 73(-1.25,6.575) 74(-1.75,6.575) 75(-2.25,6.575) 76(-2.75,6.575) 77(-3.25,6.575) 78(-3.75,6.575) 79(-4.25,6.575) 80(-4.75,6.575)
  silkscreen extent -6.7,-5.3 5.3,5.57, body extent -7,-7 7,7, height 1.52
SMB [mil] "Molded Diode, 2-Leads, Body 5.4x3.6mm, IPC Medium Density, based on OnSemi component dimensions"
  rect 85x107.99 smd: 1(-87.01,0) 2(87.01,0)
  silkscreen extent -155,-82 125,82, body extent -106,-71 106,71, height 91
SOD-523 [mm] "NXP Semiconductor recommended land pattern, nominal STEP model"
  rect 0.8x0.6 smd paste-0.05: 1(-0.55,0) 2(0.55,0)
  silkscreen extent -1.6,-0.64 1.2,0.63, body extent -0.8,-0.4 0.8,0.4, height 0.72
SOT-23 [mm] "SOT23, 3-Leads, Body 2.9x1.3mm, Pitch 0.95mm, Lead Span 2.5mm, IPC Medium Density"
  rect 1.5x0.6 smd: 1(-0.95,0.95) 2(-0.95,-0.95) 3(0.95,0)
  silkscreen extent 0.2,-1.5 0.7,1.5, body extent -1.16,-1.45 1.21,1.45, height 1
SW_FSM4JSMA [mm] "Alcoswitch"
  rect 1.4x2.1 smd: 1(2.25,4.55) 2(2.25,-4.55) 3(-2.25,4.55) 4(-2.25,-4.55)
  silkscreen extent -3,-3 3,5.4, body extent -3,-5 3,5, height 5.1
TI_Stacked_Overlay_Medium [mil]
  silkscreen extent -576,-136 576,134
TO-46 [mil] "Based on GE Measurement & Control"
  rect 45x45 hole 25: 1(-50,0)
  round 45 hole 25: 2(0,-50) 3(50,0) 4(0,50)
  silkscreen extent -113,-107 107,114, body extent -113,-106 107,114, height 107
YFQ0012AKAR [mm] "WCSP, 12-Leads, Body 1.94x1.43mm, Pitch 0.4mm"
  round 0.208 smd paste-0.13 mask+0.04: A1(-0.4,0.6) A2(0,0.6) A3(0.4,0.6) B1(-0.4,0.2) B2(0,0.2) B3(0.4,0.2) C1(-0.4,-0.2) C2(0,-0.2) C3(0.4,-0.2) D1(-0.4,-0.6) D2(0,-0.6) D3(0.4,-0.6)
  silkscreen extent -0.85,1.03 -0.75,1.12, body extent -0.71,-0.97 0.71,0.97, height 0.68

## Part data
C1 C2: "CAP, TANT, 10uF, 16V, +/-10%, 0.8 ohm, 3528-21 SMD"
C3 C4 C5 C6 C7 C8 C10 C11 C26 C27 C43 C44: "CAP, CERM, 0.1uF, 25V, +/-5%, X7R, 0603"
C9 C15 C31 C32 C33 C34 C35 C36 C37 C38 C39 C40: "CAP, CERM, 1uF, 16V, +/-10%, X7R, 0603"
C12: "CAP, CERM, 4.7uF, 10V, +/-10%, X5R, 0805"
C13: "CAP, CERM, 2.2uF, 10V, +/-10%, X5R, 0805"
C14: "CAP, CERM, 0.01uF, 16V, +/-10%, X7R, 0402"
C16 C19 C30: "CAP, CERM, 2200pF, 100V, +/-5%, X7R, 0603"
C17: library part EMVE100ADA220ME55G, "CAP ALUM 22UF 10V 20% SMD"
C18 C20: "CAP, CERM, 18pF, 50V, +/-5%, C0G/NP0, 0603"
C21 C23 C24: "CAP, CERM, 0.22uF, 10V, +/-10%, X5R, 0402"
C22: "CAP, CERM, 0.47uF, 10V, +/-10%, X5R, 0402"
C25 C29: "CAP, CERM, 10uF, 10V, +/-10%, X5R, 0805"
C28: "CAP, CERM, 0.1uF, 16V, +/-10%, X5R, 0402"
C41: "CAP, CERM, 2.2uF, 10V, +/-10%, X5R, 0603"
C42: "CAP, CERM, 1uF, 50V, +/-10%, X7R, 0805"
D1: "Diode, Zener, 7.5V, 550mW, SMB"
D2 D4: "LED, Green, SMD"
D3: "Diode, Schottky, 40V, 0.25A, SOD-523"
D5 D6 D7 D8 D9 D10: "ESD in 0402 Package with 10 pF Capacitance and 6 V Breakdown, 1 Channel, -40 to +125 degC, 2-pin X2SON (DPY), Green (RoHS & no Sb/Br)"
FID1 FID2 FID3: "Fiducial mark.  There is nothing to buy or mount."
H1 H2 H3 H4: "Machine Screw, Round, #4-40 x 1/4, Nylon, Philips panhead"
H5 H6 H7 H8: "Standoff, Hex, 0.5\"L #4-40 Nylon"
J1: "Connector, Receptacle, Mini-USB Type B, R/A, Top Mount SMT"
J2: "Header (shrouded), 100 mil, 7x2, Gold plated, TH"
J3 J5: "Header, 100mil, 2x1, Tin plated, TH"
J4: "Header, 6x2, 100mil, SMT"
L1: "6A Ferrite Bead, 26 ohm @ 100MHz, SMD"
L2 L3 L4: "1.5A Ferrite Bead, 330 ohm @ 100MHz, SMD"
L5: "Inductor, Shielded, Ferrite, 10uH, 0.47A, 0.24 ohm, SMD"
LBL1: library part THT-14-423-10, "Thermal Transfer Printable Labels, 0.650\" W x 0.200\" H - 10,000 per roll"
Logo1: library part TI_Logo, "Texas Instrument Corporate Signature"
Q1: "AMBIENT LIGHT SENSOR, SMD"
Q2 Q3: "MOSFET, N-CH, 50V, 0.22A, SOT-23"
R1 R2: "RES, 0 ohm, 5%, 0.1W, 0603"
R3: "RES, 649k ohm, 1%, 0.1W, 0603"
R4 R5 R6 R7 R8 R9: "RES, 2.21Meg ohm, 1%, 0.1W, 0603"
R10 R11: "RES, 49.9 ohm, 1%, 0.1W, 0603"
R12 R23: "RES, 200 ohm, 5%, 0.1W, 0603"
R13 R14: "RES, 1.0Meg ohm, 5%, 0.1W, 0603"
R16: "RES, 1.00k ohm, 1%, 0.1W, 0603"
R18: "RES, 0 ohm, 5%, 0.063W, 0402"
R19 R22 R26: "RES, 47.5k ohm, 1%, 0.1W, 0603"
R20 R21: "RES, 4.99k ohm, 1%, 0.063W, 0402"
R24: "RES, 1.00Meg ohm, 1%, 0.063W, 0402"
R25: "RES, 1.50k ohm, 1%, 0.063W, 0402"
S1 S2 S3: "Switch, Tactile, SPST-NO, 0.05A, 12V, SMT"
SH-J1 SH-J2: "Shunt, 2mm, Gold plated, Black"
TP1 TP2 TP3 TP4 TP14: library part 5001, "Test Point, Miniature, Black, TH"
TP5 TP6 TP7 TP8: "Test Point, Miniature, Black, TH"
TP9 TP11: "Test Point, Miniature, Orange, TH"
TP10 TP12: "Test Point, Miniature, Yellow, TH"
TP13 TP15 TP16: "Test Point, Miniature, Red, TH"
TS1: "Thermopile IR Sensor, TO-46"
U1: "16-bit analog-front-end for thermopile occupancy detector arrays, NHZ0024B"
U2: "Micropower 150 mA Low-Noise Ultra Low-Dropout Regulator, 5-pin SOT-23, Pb-Free"
U3: "Mixed Signal MicroController, PN0080A"
U4: "Low-Capacitance + / - 15 kV ESD-Protection Array for High-Speed Data Interfaces, 3 Channels, -40 to +85 degC, 5-pin SOT (DRL), Green (RoHS & no Sb/Br)"
U5: "Module, 128x64-pixel graphics display"
U6: "LM3630A High-Efficiency Dual-String White LED Driver, YFQ0012AKAR"
Y1: "Crystal, 24.000MHz, 18pF, SMD"
ZZ1: library part AssemblyNoteLabel
ZZ2 ZZ3 ZZ4 ZZ5 ZZ6 ZZ6.A ZZ6.B ZZ6.C ZZ6.D: library part AssemblyNote

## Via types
v1: diameter 24, hole 10, Top Layer to Bottom Layer, 393 vias
v2: diameter 24, hole 10, Top Layer to Bottom Layer, tented both sides, 210 vias
v3: diameter 24/24/24 (per signal layer), hole 10, Top Layer to Bottom Layer, tented both sides, 1 vias

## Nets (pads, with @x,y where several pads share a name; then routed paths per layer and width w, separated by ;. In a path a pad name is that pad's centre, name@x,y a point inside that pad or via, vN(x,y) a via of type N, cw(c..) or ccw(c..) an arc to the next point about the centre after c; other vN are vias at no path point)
+3P3V: C25.1 C26.1 C27.1 C31.1 D2.1 D4.1 J2.4 J3.1 L4.1 R1.2 R13.2 R14.2 R19.2 R20.2 R21.2 R22.2 R26.2 TP16.1 U3.18 U3.50 U5.34 U5.35 | length 10853.6
  Top Layer w8: C27.1@2778.5,2261 2778.5,2298.5 v2(2790,2310) ; U3.50@2789.84,2178.86 C27.1@2789.84,2258.34
  Top Layer w10: U3.18@2927.64,1661.14 2927.64,1601.87 C26.1@2976,1553.5
  Top Layer w15: R26.2@2660,2891.5 2660,3044 2665,3049
  Top Layer w30: 1724.5,1410 1730,1415.5 1730,2832 1947,3049 2665,3049 2709,3049 J2.4@2830,3170 ; v2(2816.34,1150) D2.1@2816.34,1215 ; R21.2@3225,2158.62 R20.2@3290,2158.62 ; R20.2@3291,2158 v2(3365,2158)
  Top Layer w40: U5.34@180,1410 1724.5,1410 2158.5,1410 v2@2419.25,1149.25 ; v2(3711,1035) 3711,982.5 R14.2@3710,981.5 R13.2@3770,981.5 3851.5,981.5 3965,1095 3965,2040 TP16.1@4100,2175
  MidLayer1 w40: v2@2400.75,1169.25 v2(2420,1150) v2(2816.34,1150) 2945,1150 3055,1260 3625,1260 3711,1174 v2(3711,1035) ; v2(2790,2310) 2790,2243 2823,2210 3313,2210 v2(3365,2158) 3598,2158 3765,2325 J3.1@3765,2550 3975,2550 4100,2425 TP16.1@4100,2175
  Bottom Layer w30: U5.35@180,1310 U5.34@180,1395 ; U5.34@187.5,1402.5 195,1410 C31.1@278.5,1410
  other v2: 2400,1168.5 3100,1260 3160,1259.5 3220,1259.5 3273.5,1259.5 3317.5,1260
+3P3V_OUT: C12.1 J3.2 U2.5 | length 278.8
  Top Layer w8: U2.5@3462.4,2627.76 3462.4,2552.6 C12.1@3465,2550
  Top Layer w30: C12.1@3465,2550 J3.2@3665,2550
+5V: C15.1 C41.1 L2.2 L5.1 U6.C3 | length 70.8
  Top Layer w8: U6.C3@2231.97,2517.13 2242.72,2517.13 2261.42,2498.43 C41.1@2295,2498.43
A0_DISP: U3.34 U5.38 | length 3331.4
  Top Layer w10: v2(2940,1985) 2943.9,1988.9 U3.34@3038.86,1988.9
  MidLayer1 w10: U5.38@180,1010 1686.09,1010 2321.09,1645 2642.09,1645 2810.09,1813 2882.54,1813 2940,1870.46 v2(2940,1985)
ADC_A0: R3.1 TS1.2 U3.77 | length 2544.7
  Top Layer w10: U3.77@2521.14,1792.05 2567.95,1792.05 2590,1770 2590,1729.61 2505,1644.61 2505,620 3022,103 R3.1@3358.5,103
  Top Layer w25: R3.1@3358.5,103 3358.5,194.5 TS1.2@3445,281
ADC_A1: U3.78
ADC_A2: C11.1 Q1.2 R16.2 U3.79 | length 378.7
  Top Layer w10: C11.1@2230,1616.5 2231.97,1614.53 Q1.2@2355,1614.53 2355,1665 2442.68,1752.68 U3.79@2521.14,1752.68
AVCC: C28.1 C29.1 C43.1 C44.1 L1.2 L4.2 Q1.1 R3.2 U3.11 | length 2690.8
  Top Layer w8: U3.11@2789.84,1661.14 2789.84,1610.16 2790,1610 C28.1@2790,1570
  Top Layer w10: C29.1@2796.38,1488.62 C29.1@2799,1486 C29.1@2800,1485
  Top Layer w20: Q1.1@2355,1555.47 2355,1481.5 C43.1@2356.5,1480 2403.5,1480 v2(2405,1478.5) ; C29.1@2796.38,1488.62 C28.1@2796.38,1570 ; C29.1@2800,1485 v2(2800,1432) 2800,1421 2821,1400 2898.5,1400 2900,1398.5 2900,680 3050,530 L1.2@3175.5,530 3175.5,488.5 v2(3175,488)
  Top Layer w30: R3.2@3421.5,103 3490.5,103 C44.1@3491.5,104 v2@3491.5,133.5
  Bottom Layer w20: v2(2405,1478.5) 2541.5,1478.5 2588,1432 v2(2800,1432) ; v2(3175,488) 3175,249.5 3288.5,136 v2(3491.5,136)
BL_EN: U3.31 U6.B1 | length 2480
  Top Layer w8: v2(2130,2515) 2147.87,2532.87 U6.B1@2199.25,2532.87 ; U3.31@3038.86,1929.84 3104.84,1929.84 v2(3120,1945)
  MidLayer1 w8: v2(2130,2515) 2126,2511 2126,2322.94 2139,2309.94 2139,2011 2229,1921 2395,1921 2446,1870 2572,1870 2659,1957 2659,2117 2707,2165 3293.94,2165 3339,2119.94 3339,2085 3199,1945 v2(3120,1945)
BL_PWM: U3.30 U6.C1 | length 2466.7
  Top Layer w8: v2(2150,2475) 2150,2488.5 2178.62,2517.13 U6.C1@2199.25,2517.13 ; U3.30@3038.86,1910.16 3130.16,1910.16 3135,1915 v2(3136,1914)
  MidLayer1 w8: v2(2150,2475) 2155,2470 2155,2017.63 2235.63,1937 2403,1937 2454,1886 2565.37,1886 2643,1963.63 2643,2123.63 2651.5,2132.13 2651.5,2133.5 2699,2181 3300.57,2181 3355,2126.57 3355,2075 3195,1915 3135,1915 v2(3136,1914)
BLSW: D3.2 L5.2 U6.A3 | length 272
  Top Layer w8: U6.A3@2230.75,2548.62 2230.75,2577.75 ; D3.2@2398.15,2616.5 D3.2@2400,2618.35
  Top Layer w15: 2230.75,2577.75 2269.5,2616.5 D3.2@2398.15,2616.5 ; L5.2@2400,2561.57 D3.2@2400,2618.35
CS_AFE: U1.15 U3.29 | length 1259
  Top Layer w8: U3.29@3038.86,1890.47 3039.33,1890 3145.94,1890 3146.41,1890.47 3179.53,1890.47 3515,1555 3515,1018 3493,996 3493,921.49 U1.15@3493.62,920.87
DRDYB: R10.2 U3.33 | length 1193.9
  Top Layer w10: U3.33@3038.86,1969.21 3039.65,1970 3145,1970 v2(3160,1985)
  Bottom Layer w10: v2(3160,1985) 3165,1980 3165,1619.04 3565,1219.04 R10.2@3565,1086.5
